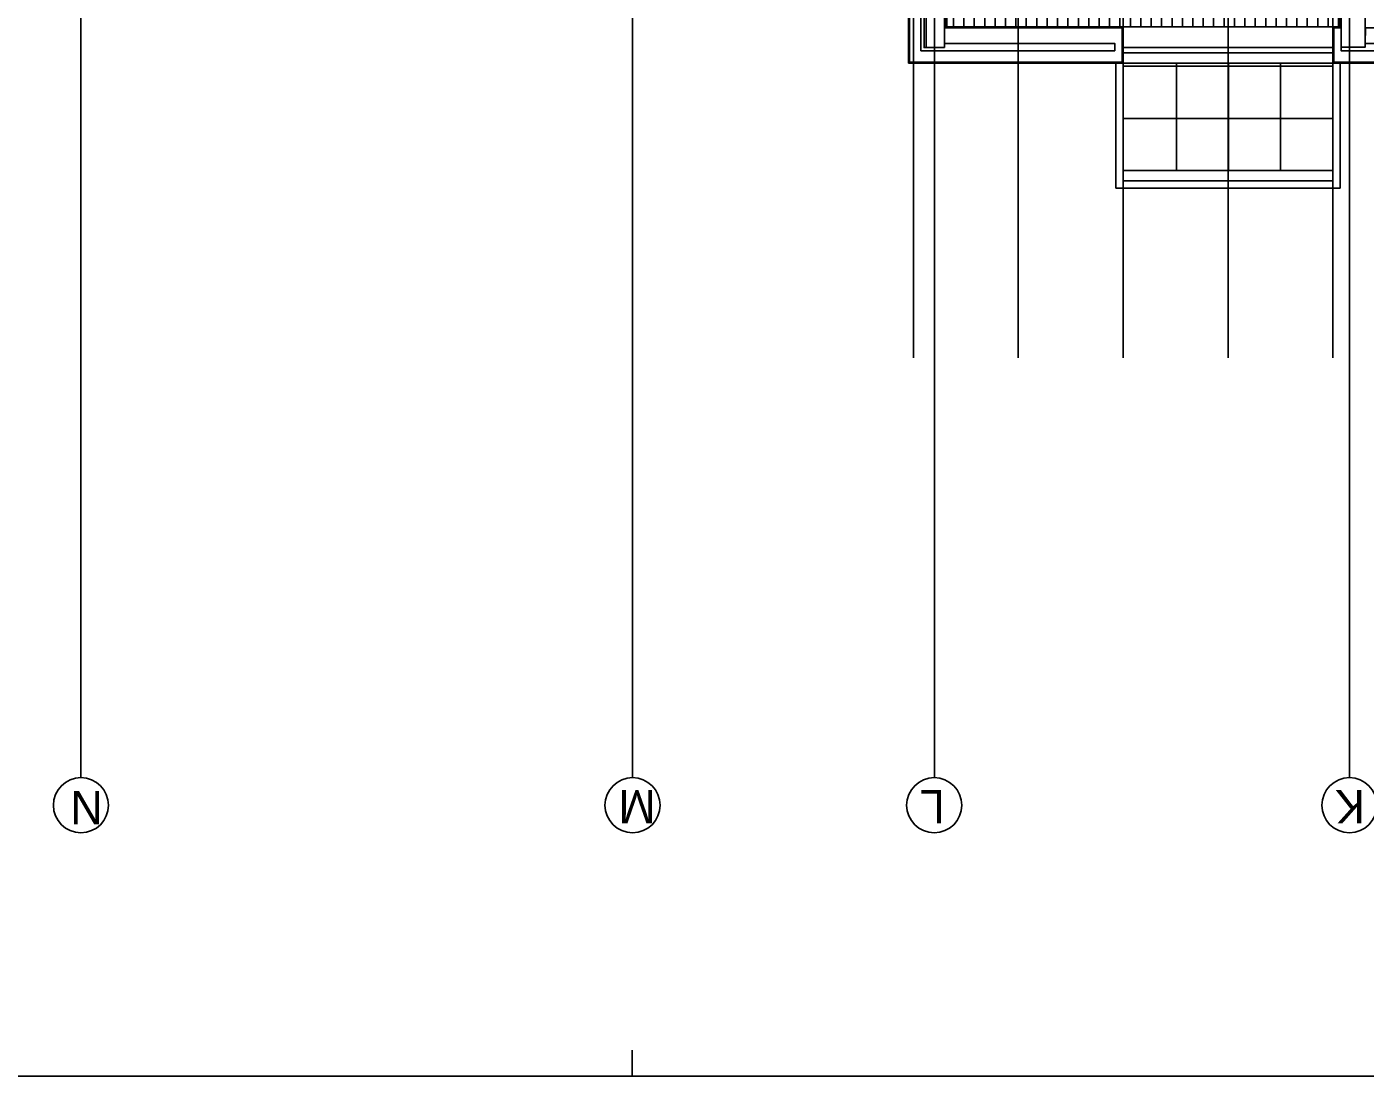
# Model space of a CAD drawing. Extents: x 1278 to 1356, y -253.7 to -224.
# Drawn here: x 1290.7 to 1303.56, y -253.66 to -243.57 of the extents above; entities that cross this region are included whole.
import ezdxf

# ---------------------------------------------------------------- set-up
doc = ezdxf.new("R2010")
doc.units = 0
for name, color, linetype in [('Level 1', 7, 'Continuous'), ('Level 10', 7, 'Continuous'), ('Level 2', 7, 'Continuous'), ('Level 40', 7, 'Continuous'), ('Level 62', 7, 'Continuous'), ('Level 65', 7, 'Continuous'), ('Level 66', 7, 'Continuous'), ('Level 67', 7, 'Continuous'), ('Level 68', 7, 'Continuous'), ('Level 70', 7, 'Continuous'), ('Level 93', 7, 'Continuous')]:
    doc.layers.add(name, color=color, linetype=linetype)

msp = doc.modelspace()

# ---------------------------------------------------------------- linework, layer by layer
at = {"layer": 'Level 1'}
for p, q in [((1299.291, -243.804), (1299.291, -236.689)), ((1299.181, -243.914), (1299.181, -236.799)), ((1299.343, -243.774), (1299.343, -239.304)), ((1301.224, -243.584), (1299.53, -243.584)), ((1301.224, -243.914), (1301.224, -243.584)), ((1301.154, -243.804), (1301.154, -243.734)), ((1301.154, -243.804), (1299.291, -243.804)), ((1303.258, -243.914), (1305.254, -243.914))]:
    msp.add_line(p, q, dxfattribs=at)
at = {"layer": 'Level 10'}
for p, q in [((1299.604, -243.574), (1299.604, -235.155)), ((1299.704, -243.574), (1299.704, -235.155)), ((1299.804, -243.574), (1299.804, -235.155)), ((1299.904, -243.574), (1299.904, -235.155)), ((1300.004, -243.574), (1300.004, -235.155)), ((1300.104, -243.574), (1300.104, -235.155)), ((1300.204, -243.574), (1300.204, -235.155)), ((1300.304, -243.574), (1300.304, -235.155)), ((1300.404, -243.574), (1300.404, -235.155)), ((1300.504, -243.574), (1300.504, -235.155)), ((1300.604, -243.574), (1300.604, -235.155)), ((1300.704, -243.574), (1300.704, -235.155)), ((1300.804, -243.574), (1300.804, -235.155)), ((1300.904, -243.574), (1300.904, -235.155)), ((1301.004, -243.574), (1301.004, -238.974)), ((1301.104, -243.574), (1301.104, -239.076)), ((1301.204, -243.574), (1301.204, -239.076)), ((1301.304, -243.574), (1301.304, -239.076)), ((1301.404, -243.574), (1301.404, -239.076)), ((1301.504, -243.574), (1301.504, -239.076)), ((1301.604, -243.574), (1301.604, -239.076)), ((1301.704, -243.574), (1301.704, -239.076)), ((1301.804, -243.574), (1301.804, -239.076)), ((1301.904, -243.574), (1301.904, -239.076)), ((1302.004, -243.574), (1302.004, -239.076)), ((1302.104, -243.574), (1302.104, -239.076)), ((1302.204, -243.574), (1302.204, -239.076)), ((1302.304, -243.574), (1302.304, -239.076)), ((1302.404, -243.574), (1302.404, -239.076)), ((1302.504, -243.574), (1302.504, -239.076)), ((1302.604, -243.574), (1302.604, -239.076)), ((1302.704, -243.574), (1302.704, -239.076)), ((1302.804, -243.574), (1302.804, -239.076)), ((1302.904, -243.574), (1302.904, -239.076)), ((1303.004, -243.574), (1303.004, -239.076)), ((1303.104, -243.574), (1303.104, -239.076)), ((1303.204, -243.574), (1303.204, -239.076)), ((1303.304, -243.574), (1303.304, -239.076)), ((1303.249, -243.954), (1301.234, -243.954)), ((1301.747, -244.954), (1301.747, -243.924)), ((1302.247, -244.954), (1302.247, -243.924)), ((1302.747, -244.954), (1302.747, -243.924)), ((1303.249, -244.454), (1301.234, -244.454)), ((1303.249, -244.954), (1301.234, -244.954))]:
    msp.add_line(p, q, dxfattribs=at)
at = {"layer": 'Level 2'}
for p, q in [((1303.249, -243.574), (1301.234, -243.574)), ((1303.249, -243.774), (1301.234, -243.774)), ((1303.249, -243.824), (1301.234, -243.824)), ((1301.164, -245.124), (1301.164, -243.924)), ((1303.249, -243.924), (1301.234, -243.924)), ((1301.234, -245.054), (1301.234, -243.924)), ((1303.249, -245.054), (1303.249, -243.924)), ((1303.319, -245.124), (1303.319, -243.924)), ((1303.319, -245.124), (1301.164, -245.124)), ((1303.249, -245.054), (1301.234, -245.054))]:
    msp.add_line(p, q, dxfattribs=at)
at = {"layer": 'Level 40'}
for centre in [(1291.219, -251.055), (1296.52, -251.055), (1299.419, -251.055), (1303.409, -251.055)]:
    msp.add_circle(centre, 0.265, dxfattribs=at)
at = {"layer": 'Level 62'}
msp.add_lwpolyline([(1355.966, -223.959), (1355.966, -253.659), (1278.016, -253.659), (1278.016, -223.959)], close=True, dxfattribs=at)
at = {"layer": 'Level 65'}
for p, q in [((1299.54, -243.574), (1299.54, -235.155)), ((1299.171, -243.924), (1299.171, -236.819)), ((1303.319, -243.574), (1303.319, -239.076)), ((1299.54, -243.574), (1301.234, -243.574)), ((1301.234, -243.924), (1301.234, -243.574)), ((1303.249, -243.574), (1303.249, -243.924)), ((1303.319, -243.574), (1303.249, -243.574)), ((1303.249, -243.924), (1303.249, -243.75)), ((1299.171, -243.924), (1301.234, -243.924)), ((1303.249, -243.924), (1305.264, -243.924))]:
    msp.add_line(p, q, dxfattribs=at)
at = {"layer": 'Level 66'}
for p, q in [((1299.53, -243.584), (1299.53, -232.264)), ((1303.258, -243.914), (1303.258, -243.584)), ((1303.258, -243.584), (1303.329, -243.584)), ((1303.329, -243.804), (1303.329, -243.584)), ((1301.154, -243.734), (1299.519, -243.734)), ((1305.184, -243.804), (1303.329, -243.804)), ((1299.181, -243.914), (1301.224, -243.914))]:
    msp.add_line(p, q, dxfattribs=at)
for points in [[(1299.519, -243.774), (1299.321, -243.774), (1299.321, -236.639), (1299.519, -236.639)], [(1303.329, -243.771), (1303.559, -243.771), (1303.559, -242.871), (1303.329, -242.871)], [(1303.329, -243.771), (1303.559, -243.771), (1303.559, -242.871), (1303.329, -242.871)]]:
    msp.add_lwpolyline(points, close=True, dxfattribs=at)
at = {"layer": 'Level 67'}
for points in [[(1296.553, -230.87), (1293.074, -230.87), (1293.074, -231.17), (1296.404, -231.17), (1296.404, -236.799), (1299.181, -236.799), (1299.181, -243.914), (1301.224, -243.914), (1301.224, -243.584), (1299.519, -243.584), (1299.519, -243.734), (1301.154, -243.734), (1301.154, -243.804), (1299.291, -243.804), (1299.291, -236.689), (1296.514, -236.689), (1296.514, -231.17), (1296.514, -231.02), (1293.144, -231.02), (1293.144, -230.98), (1296.553, -230.98)], [(1303.562, -243.584), (1305.254, -243.584), (1305.254, -243.914), (1303.258, -243.914), (1303.258, -243.584), (1303.329, -243.584), (1303.329, -243.804), (1305.184, -243.804), (1305.184, -243.734), (1303.559, -243.734)]]:
    msp.add_lwpolyline(points, close=True, dxfattribs=at)
at = {"layer": 'Level 68'}
msp.add_line((1296.516, -253.659), (1296.516, -253.409), dxfattribs=at)
at = {"layer": 'Level 70'}
for p, q in [((1291.219, -225.567), (1291.219, -250.792)), ((1296.519, -250.792), (1296.519, -225.567)), ((1299.42, -250.792), (1299.42, -225.567)), ((1303.409, -250.792), (1303.409, -229.609))]:
    msp.add_line(p, q, dxfattribs=at)
at = {"layer": 'Level 93'}
for p, q in [((1299.219, -246.757), (1299.219, -236.141)), ((1300.227, -246.757), (1300.227, -236.141)), ((1301.234, -246.757), (1301.234, -236.141)), ((1302.242, -246.757), (1302.242, -236.141)), ((1303.249, -246.757), (1303.249, -236.141))]:
    msp.add_line(p, q, dxfattribs=at)

# ---------------------------------------------------------------- texts
at = {"layer": 'Level 40'}
for s, p in [('N', (1291.427, -250.918)), ('M', (1296.741, -250.909)), ('L', (1299.519, -250.909)), ('K', (1303.558, -250.909))]:
    msp.add_text(s, height=0.32, rotation=180, dxfattribs=at).set_placement(p)

doc.saveas('drawing.dxf')
